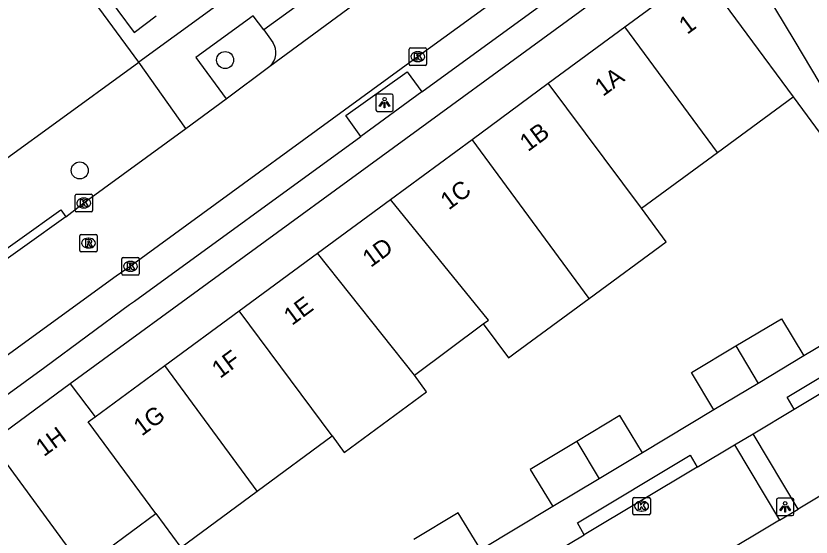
# Model space of a CAD drawing. Extents: x 161771 to 163125, y 382479 to 383177.
# Drawn here: x 162223.18 to 162268.84, y 382940.98 to 382970.92 of the extents above; entities that cross this region are included whole.
import ezdxf

# ---------------------------------------------------------------- set-up
doc = ezdxf.new("R2010")
doc.units = 0
for name, color, linetype in [('IMGEO_Boom', 7, 'Continuous'), ('IMGEO_Haag', 7, 'Continuous'), ('IMGEO_Kolk', 7, 'Continuous'), ('IMGEO_Lichtpunt', 7, 'Continuous'), ('IMGEO_Pand', 7, 'Continuous'), ('IMGEO_Pand_nummerreeks', 7, 'Continuous'), ('IMGEO_Parkeervlak_open', 7, 'Continuous'), ('IMGEO_Rijbaan_lokaal_open', 7, 'Continuous'), ('IMGEO_Rioolput', 7, 'Continuous'), ('IMGEO_Voetpad_open', 7, 'Continuous')]:
    doc.layers.add(name, color=color, linetype=linetype)

msp = doc.modelspace()

# ---------------------------------------------------------------- linework, layer by layer
at = {"layer": 'IMGEO_Boom'}
for centre in [(162235.197, 382968.385), (162226.847, 382962.044)]:
    msp.add_circle(centre, 0.489, dxfattribs=at)
at = {"layer": 'IMGEO_Haag'}
msp.add_lwpolyline([(162230.248, 382968.265), (162227.462, 382972.043), (162228.1, 382972.513)], dxfattribs=at)
at = {"layer": 'IMGEO_Kolk'}
for p, q in [((162245.757, 382968.15), (162245.757, 382969.002)), ((162245.832, 382969.076), (162246.684, 382969.076)), ((162246.245, 382968.856), (162246.27, 382968.856)), ((162246.758, 382969.002), (162246.758, 382968.15)), ((162246.684, 382968.076), (162245.832, 382968.076)), ((162246.268, 382968.296), (162246.243, 382968.296)), ((162226.653, 382960.67), (162227.505, 382960.67)), ((162226.578, 382959.744), (162226.578, 382960.596)), ((162227.066, 382960.45), (162227.091, 382960.45)), ((162227.579, 382960.596), (162227.579, 382959.744)), ((162227.089, 382959.89), (162227.064, 382959.89)), ((162227.505, 382959.67), (162226.653, 382959.67)), ((162229.339, 382957.034), (162230.191, 382957.034)), ((162229.264, 382956.108), (162229.264, 382956.96)), ((162229.752, 382956.814), (162229.777, 382956.814)), ((162230.265, 382956.96), (162230.265, 382956.108)), ((162229.775, 382956.254), (162229.75, 382956.254)), ((162230.191, 382956.034), (162229.339, 382956.034)), ((162258.608, 382942.332), (162258.608, 382943.184)), ((162258.683, 382943.258), (162259.535, 382943.258)), ((162259.096, 382943.038), (162259.121, 382943.038)), ((162259.609, 382943.184), (162259.609, 382942.332)), ((162259.119, 382942.478), (162259.094, 382942.478)), ((162259.535, 382942.258), (162258.683, 382942.258))]:
    msp.add_line(p, q, dxfattribs=at)
for points in [[(162245.757, 382968.15), (162245.757, 382969.002)], [(162245.832, 382969.076), (162246.684, 382969.076)], [(162246.758, 382969.002), (162246.758, 382968.15)], [(162246.078, 382968.776), (162246.201, 382968.776), (162246.201, 382968.625), (162246.331, 382968.776), (162246.495, 382968.776), (162246.349, 382968.625), (162246.502, 382968.376), (162246.35, 382968.376), (162246.265, 382968.54), (162246.201, 382968.473), (162246.201, 382968.376), (162246.078, 382968.376), (162246.078, 382968.776)], [(162246.684, 382968.076), (162245.832, 382968.076)], [(162226.653, 382960.67), (162227.505, 382960.67)], [(162226.578, 382959.744), (162226.578, 382960.596)], [(162226.899, 382960.37), (162227.022, 382960.37), (162227.022, 382960.219), (162227.152, 382960.37), (162227.316, 382960.37), (162227.17, 382960.219), (162227.323, 382959.97), (162227.171, 382959.97), (162227.086, 382960.134), (162227.022, 382960.067), (162227.022, 382959.97), (162226.899, 382959.97), (162226.899, 382960.37)], [(162227.579, 382960.596), (162227.579, 382959.744)], [(162227.505, 382959.67), (162226.653, 382959.67)], [(162229.339, 382957.034), (162230.191, 382957.034)], [(162229.264, 382956.108), (162229.264, 382956.96)], [(162229.585, 382956.734), (162229.708, 382956.734), (162229.708, 382956.583), (162229.838, 382956.734), (162230.002, 382956.734), (162229.856, 382956.583), (162230.009, 382956.334), (162229.857, 382956.334), (162229.772, 382956.498), (162229.708, 382956.431), (162229.708, 382956.334), (162229.585, 382956.334), (162229.585, 382956.734)], [(162230.265, 382956.96), (162230.265, 382956.108)], [(162230.191, 382956.034), (162229.339, 382956.034)], [(162258.608, 382942.332), (162258.608, 382943.184)], [(162258.683, 382943.258), (162259.535, 382943.258)], [(162258.929, 382942.958), (162259.052, 382942.958), (162259.052, 382942.807), (162259.182, 382942.958), (162259.346, 382942.958), (162259.2, 382942.807), (162259.353, 382942.558), (162259.201, 382942.558), (162259.116, 382942.722), (162259.052, 382942.655), (162259.052, 382942.558), (162258.929, 382942.558), (162258.929, 382942.958)], [(162259.609, 382943.184), (162259.609, 382942.332)], [(162259.535, 382942.258), (162258.683, 382942.258)]]:
    msp.add_lwpolyline(points, dxfattribs=at)
for centre, start, end in [((162245.834, 382969), 91.552, 178.448), ((162245.834, 382969), 91.552, 178.448), ((162246.682, 382969), 1.552, 88.448), ((162246.682, 382969), 1.552, 88.448), ((162245.834, 382968.152), 181.552, 268.448), ((162245.834, 382968.152), 181.552, 268.448), ((162246.682, 382968.152), 271.552, 358.448), ((162246.682, 382968.152), 271.552, 358.448), ((162226.655, 382960.594), 91.552, 178.448), ((162226.655, 382960.594), 91.552, 178.448), ((162227.503, 382960.594), 1.552, 88.448), ((162227.503, 382960.594), 1.552, 88.448), ((162226.655, 382959.746), 181.552, 268.448), ((162226.655, 382959.746), 181.552, 268.448), ((162227.503, 382959.746), 271.552, 358.448), ((162227.503, 382959.746), 271.552, 358.448), ((162229.341, 382956.958), 91.552, 178.448), ((162229.341, 382956.958), 91.552, 178.448), ((162230.189, 382956.958), 1.552, 88.448), ((162230.189, 382956.958), 1.552, 88.448), ((162229.341, 382956.11), 181.552, 268.448), ((162229.341, 382956.11), 181.552, 268.448), ((162230.189, 382956.11), 271.552, 358.448), ((162230.189, 382956.11), 271.552, 358.448), ((162258.685, 382943.182), 91.552, 178.448), ((162258.685, 382943.182), 91.552, 178.448), ((162259.533, 382943.182), 1.552, 88.448), ((162259.533, 382943.182), 1.552, 88.448), ((162258.685, 382942.334), 181.552, 268.448), ((162258.685, 382942.334), 181.552, 268.448), ((162259.533, 382942.334), 271.552, 358.448), ((162259.533, 382942.334), 271.552, 358.448)]:
    msp.add_arc(centre, 0.0765, start, end, dxfattribs=at)
for centre, major_axis, ratio, start_param, end_param in [((162246.244, 382968.576), (-0.387, 0.002), 0.722429, 4.712389, 7.853982), ((162246.269, 382968.576), (-0.39, 0.002), 0.717154, 1.570796, 4.712389), ((162227.065, 382960.17), (-0.387, 0.002), 0.722429, 4.712389, 7.853982), ((162227.09, 382960.17), (-0.39, 0.002), 0.717154, 1.570796, 4.712389), ((162229.751, 382956.534), (-0.387, 0.002), 0.722429, 4.712389, 7.853982), ((162229.776, 382956.534), (-0.39, 0.002), 0.717154, 1.570796, 4.712389), ((162259.095, 382942.758), (-0.387, 0.002), 0.722429, 4.712389, 7.853982), ((162259.12, 382942.758), (-0.39, 0.002), 0.717154, 1.570796, 4.712389)]:
    msp.add_ellipse(centre, major_axis=major_axis, ratio=ratio, start_param=start_param, end_param=end_param, dxfattribs=at)
at = {"layer": 'IMGEO_Lichtpunt'}
for p, q in [((162243.851, 382966.335), (162243.851, 382965.528)), ((162243.851, 382966.335), (162243.851, 382965.528)), ((162244.753, 382966.43), (162243.945, 382966.43)), ((162244.753, 382966.43), (162243.945, 382966.43)), ((162244.847, 382965.528), (162244.847, 382966.335)), ((162244.847, 382965.528), (162244.847, 382966.335)), ((162243.945, 382965.434), (162244.753, 382965.434)), ((162243.945, 382965.434), (162244.753, 382965.434)), ((162266.852, 382943.12), (162266.852, 382942.313)), ((162266.852, 382943.12), (162266.852, 382942.313)), ((162267.754, 382943.215), (162266.946, 382943.215)), ((162267.754, 382943.215), (162266.946, 382943.215)), ((162267.848, 382942.313), (162267.848, 382943.12)), ((162267.848, 382942.313), (162267.848, 382943.12)), ((162266.946, 382942.219), (162267.754, 382942.219)), ((162266.946, 382942.219), (162267.754, 382942.219))]:
    msp.add_line(p, q, dxfattribs=at)
for points in [[(162244.225, 382965.999), (162244.264, 382965.971), (162244.076, 382965.709), (162244.038, 382965.736), (162244.225, 382965.999)], [(162244.327, 382965.951), (162244.374, 382965.951), (162244.374, 382965.629), (162244.327, 382965.629), (162244.327, 382965.951)], [(162244.437, 382965.971), (162244.475, 382965.998), (162244.662, 382965.736), (162244.623, 382965.708), (162244.437, 382965.971)], [(162267.226, 382942.784), (162267.265, 382942.756), (162267.077, 382942.494), (162267.039, 382942.521), (162267.226, 382942.784)], [(162267.328, 382942.736), (162267.375, 382942.736), (162267.375, 382942.414), (162267.328, 382942.414), (162267.328, 382942.736)], [(162267.438, 382942.756), (162267.476, 382942.783), (162267.663, 382942.521), (162267.624, 382942.493), (162267.438, 382942.756)]]:
    msp.add_lwpolyline(points, dxfattribs=at)
for centre in [(162244.35, 382966.133), (162267.351, 382942.918)]:
    msp.add_circle(centre, 0.0994, dxfattribs=at)
for centre, start, end in [((162243.945, 382966.335), 90, 180), ((162243.945, 382966.335), 90, 180), ((162244.753, 382966.335), 0, 90), ((162244.753, 382966.335), 0, 90), ((162243.945, 382965.528), 180, 270), ((162243.945, 382965.528), 180, 270), ((162244.753, 382965.528), 270, 0), ((162244.753, 382965.528), 270, 360), ((162266.946, 382943.12), 90, 180), ((162266.946, 382943.12), 90, 180), ((162267.754, 382943.12), 0, 90), ((162267.754, 382943.12), 0, 90), ((162266.946, 382942.313), 180, 270), ((162266.946, 382942.313), 180, 270), ((162267.754, 382942.313), 270, 0), ((162267.754, 382942.313), 270, 360)]:
    msp.add_arc(centre, 0.0946, start, end, dxfattribs=at)
at = {"layer": 'IMGEO_Pand'}
for points in [[(162269.788, 382966.328), (162267.921, 382969.44), (162263.426, 382976.923)], [(162258.151, 382970.295), (162262.493, 382973.494), (162267.802, 382966.277)], [(162253.752, 382967.054), (162258.151, 382970.295)], [(162263.459, 382963.08), (162258.151, 382970.295)], [(162249.372, 382963.828), (162253.752, 382967.054)], [(162259.095, 382959.867), (162253.752, 382967.054)], [(162263.459, 382963.08), (162267.802, 382966.277)], [(162244.693, 382960.38), (162249.372, 382963.828)], [(162256.096, 382954.687), (162249.372, 382963.828)], [(162259.095, 382959.867), (162263.459, 382963.08)], [(162240.496, 382957.288), (162244.693, 382960.38)], [(162250.014, 382953.222), (162250.315, 382953.446), (162244.693, 382960.38)], [(162256.096, 382954.687), (162260.512, 382957.943), (162259.095, 382959.867)], [(162235.993, 382953.97), (162240.496, 382957.288)], [(162246.066, 382950.281), (162240.496, 382957.288)], [(162250.014, 382953.222), (162251.47, 382951.276), (162251.849, 382951.555), (162256.096, 382954.687)], [(162231.73, 382950.83), (162235.993, 382953.97)], [(162241.332, 382946.788), (162235.993, 382953.97)], [(162264.516, 382951.957), (162267.136, 382953.527), (162268.421, 382951.383)], [(162246.066, 382950.281), (162250.014, 382953.222)], [(162263.258, 382948.288), (162261.973, 382950.432), (162264.516, 382951.957)], [(162264.516, 382951.957), (162265.799, 382949.811)], [(162268.421, 382951.383), (162265.799, 382949.811)], [(162227.725, 382947.879), (162231.73, 382950.83)], [(162237.032, 382943.621), (162231.73, 382950.83)], [(162241.332, 382946.788), (162242.035, 382945.834), (162246.767, 382949.316), (162246.066, 382950.281)], [(162226.3, 382949.775), (162221.74, 382946.434)], [(162226.3, 382949.775), (162227.725, 382947.879)], [(162265.799, 382949.811), (162263.258, 382948.288)], [(162231.214, 382942.329), (162227.34, 382947.595), (162227.725, 382947.879)], [(162259.155, 382945.829), (162257.866, 382947.971), (162255.382, 382946.476)], [(162237.032, 382943.621), (162241.332, 382946.788)], [(162255.382, 382946.476), (162252.715, 382944.871), (162254.004, 382942.729)], [(162255.382, 382946.476), (162256.664, 382944.33)], [(162227.033, 382939.239), (162221.74, 382946.434)], [(162259.155, 382945.829), (162256.664, 382944.33)], [(162256.664, 382944.33), (162254.004, 382942.729)], [(162231.214, 382942.329), (162232.645, 382940.391), (162237.032, 382943.621)], [(162249.875, 382940.239), (162248.584, 382942.38), (162246.039, 382940.845)], [(162227.033, 382939.239), (162231.214, 382942.329)]]:
    msp.add_lwpolyline(points, dxfattribs=at)
at = {"layer": 'IMGEO_Parkeervlak_open'}
for points in [[(162242.985, 382963.986), (162242.124, 382965.19), (162245.653, 382967.71), (162246.495, 382966.548)], [(162267.864, 382948.336), (162276.238, 382953.336)], [(162268.09, 382942.581), (162265.506, 382946.909)], [(162264.432, 382946.273), (162267.028, 382941.961)], [(162262.296, 382945.001), (162255.819, 382941.114)]]:
    msp.add_lwpolyline(points, dxfattribs=at)
at = {"layer": 'IMGEO_Rijbaan_lokaal_open'}
for points in [[(162267.496, 382984.057), (162264.451, 382981.801), (162246.219, 382968.548), (162229.741, 382956.526), (162228.942, 382955.97), (162223.752, 382952.192), (162210.859, 382942.768)], [(162237.755, 382968.034), (162244.764, 382973.197)], [(162235.265, 382966.151), (162237.755, 382968.034)], [(162232.935, 382964.45), (162235.265, 382966.151)], [(162226.044, 382959.373), (162227.078, 382960.175), (162232.935, 382964.45)], [(162226.044, 382959.373), (162221.328, 382956.001)], [(162278.832, 382949.014), (162268.09, 382942.581)], [(162267.028, 382941.961), (162268.09, 382942.581)], [(162267.028, 382941.961), (162256.198, 382935.466)]]:
    msp.add_lwpolyline(points, dxfattribs=at)
at = {"layer": 'IMGEO_Rioolput'}
for p, q in [((162226.924, 382958.367), (162227.776, 382958.367)), ((162226.849, 382957.441), (162226.849, 382958.293)), ((162227.337, 382958.147), (162227.362, 382958.147)), ((162227.85, 382958.293), (162227.85, 382957.441)), ((162227.36, 382957.587), (162227.335, 382957.587)), ((162227.776, 382957.367), (162226.924, 382957.367))]:
    msp.add_line(p, q, dxfattribs=at)
for points in [[(162226.924, 382958.367), (162227.776, 382958.367)], [(162226.849, 382957.441), (162226.849, 382958.293)], [(162227.438, 382958.065), (162227.186, 382958.067), (162227.186, 382957.667)], [(162227.364, 382957.986), (162227.31, 382957.986), (162227.31, 382957.905)], [(162227.31, 382957.905), (162227.362, 382957.905)], [(162227.85, 382958.293), (162227.85, 382957.441)], [(162227.186, 382957.667), (162227.31, 382957.667), (162227.31, 382957.829), (162227.321, 382957.829)], [(162227.368, 382957.8), (162227.439, 382957.667), (162227.579, 382957.667), (162227.514, 382957.793)], [(162227.776, 382957.367), (162226.924, 382957.367)]]:
    msp.add_lwpolyline(points, dxfattribs=at)
for centre, radius, start, end in [((162226.926, 382958.291), 0.0765, 91.552, 178.448), ((162226.926, 382958.291), 0.0765, 91.552, 178.448), ((162227.774, 382958.291), 0.0765, 1.552, 88.448), ((162227.774, 382958.291), 0.0765, 1.552, 88.448), ((162227.346, 382958.094), 0.19, 274.7715, 282.9687), ((162227.37, 382957.89), 0.0964, 77.0061, 93.1865), ((162227.384, 382957.947), 0.0378, 276.6634, 79.6772), ((162227.437, 382957.955), 0.109, 350.3612, 89.416), ((162227.435, 382957.955), 0.112, 277.5842, 350.9817), ((162226.926, 382957.443), 0.0765, 181.552, 268.448), ((162226.926, 382957.443), 0.0765, 181.552, 268.448), ((162227.32, 382957.776), 0.0533, 26.0293, 88.6989), ((162227.419, 382957.74), 0.108, 29.5134, 73.7905), ((162227.774, 382957.443), 0.0765, 271.552, 358.448), ((162227.774, 382957.443), 0.0765, 271.552, 358.448)]:
    msp.add_arc(centre, radius, start, end, dxfattribs=at)
for centre, major_axis, ratio, start_param, end_param in [((162227.336, 382957.867), (-0.387, 0.002), 0.722429, 4.712389, 7.853982), ((162227.361, 382957.867), (-0.39, 0.002), 0.717154, 1.570796, 4.712389)]:
    msp.add_ellipse(centre, major_axis=major_axis, ratio=ratio, start_param=start_param, end_param=end_param, dxfattribs=at)
at = {"layer": 'IMGEO_Voetpad_open'}
for points in [[(162264.363, 382993.075), (162263.971, 382992.79), (162230.248, 382968.265)], [(162246.495, 382966.548), (162264.048, 382979.339), (162267.784, 382982.129)], [(162263.426, 382976.923), (162226.3, 382949.775)], [(162243.028, 382974.201), (162237.42, 382970.118)], [(162228.1, 382972.513), (162229.965, 382969.972), (162231.229, 382970.922)], [(162237.42, 382970.118), (162236.811, 382970.916), (162233.51, 382968.524), (162235.265, 382966.151)], [(162237.42, 382970.118), (162237.713, 382969.724), (162237.926, 382969.384)], [(162194.009, 382944.334), (162195.249, 382942.651), (162218.576, 382959.777), (162223.093, 382963.062), (162225.238, 382964.622), (162230.248, 382968.265)], [(162232.935, 382964.45), (162230.248, 382968.265)], [(162246.495, 382966.548), (162242.985, 382963.986)], [(162267.802, 382966.277), (162271.446, 382961.323), (162275.032, 382955.334), (162273.056, 382954.151)], [(162211.712, 382941.6), (162211.909, 382941.33), (162224.84, 382950.737), (162229.71, 382954.342), (162229.996, 382954.529), (162242.985, 382963.986)], [(162221.328, 382956.001), (162221.038, 382956.407), (162225.754, 382959.779), (162226.044, 382959.373)], [(162267.864, 382948.336), (162267.469, 382949.025), (162275.813, 382954.03), (162276.238, 382953.336)], [(162270.456, 382952.602), (162268.421, 382951.383)], [(162265.506, 382946.909), (162267.864, 382948.336)], [(162263.258, 382948.288), (162259.155, 382945.829)], [(162264.432, 382946.273), (162265.506, 382946.909)], [(162262.296, 382945.001), (162264.432, 382946.273)], [(162255.819, 382941.114), (162255.42, 382941.795), (162261.891, 382945.677), (162262.296, 382945.001)], [(162254.004, 382942.729), (162249.875, 382940.239)], [(162253.59, 382939.781), (162255.819, 382941.114)]]:
    msp.add_lwpolyline(points, dxfattribs=at)
msp.add_arc((162237.129, 382968.799), 0.989, 309.3014, 36.2606, dxfattribs=at)

# ---------------------------------------------------------------- texts
at = {"layer": 'IMGEO_Pand_nummerreeks'}
for s, rotation, p in [('1', 36.3808, (162261.724, 382969.822)), ('1', 36.3808, (162261.724, 382969.822)), ('1A', 36.3808, (162256.888, 382966.259)), ('1B', 36.3808, (162252.583, 382963.088)), ('1C', 36.3808, (162248.032, 382959.735)), ('1D', 36.3808, (162243.553, 382956.435)), ('1E', 36.3808, (162239.032, 382953.104)), ('1F', 36.3808, (162234.902, 382950.061)), ('1G', 36.3808, (162230.409, 382946.751)), ('1G', 36.3808, (162230.409, 382946.751)), ('1G', 36.3808, (162230.409, 382946.751)), ('1G', 36.3808, (162230.409, 382946.751)), ('1G', 36.3808, (162230.409, 382946.751)), ('1G', 36.3808, (162230.409, 382946.751)), ('1G', 36.3808, (162230.409, 382946.751)), ('1G', 36.3808, (162230.409, 382946.751)), ('1G', 36.3808, (162230.409, 382946.751)), ('1G', 36.3808, (162230.409, 382946.751)), ('1G', 36.3808, (162230.409, 382946.751)), ('1G', 36.3808, (162230.409, 382946.751)), ('1G', 36.3808, (162230.409, 382946.751)), ('1G', 36.3808, (162230.409, 382946.751)), ('1G', 36.3808, (162230.409, 382946.751)), ('1G', 36.3808, (162230.409, 382946.751)), ('1G', 36.3808, (162230.409, 382946.751)), ('1G', 36.3808, (162230.409, 382946.751)), ('1G', 36.3808, (162230.409, 382946.751)), ('1G', 36.3808, (162230.409, 382946.751)), ('1G', 36.3808, (162230.409, 382946.751)), ('1G', 36.3808, (162230.409, 382946.751)), ('1G', 36.3808, (162230.409, 382946.751)), ('1G', 36.3808, (162230.409, 382946.751)), ('1G', 36.3828, (162230.41, 382946.751)), ('1G', 36.3828, (162230.41, 382946.751)), ('1H', 36.229, (162224.787, 382945.568))]:
    msp.add_text(s, height=1, rotation=rotation, dxfattribs=at).set_placement(p)

doc.saveas('drawing.dxf')
